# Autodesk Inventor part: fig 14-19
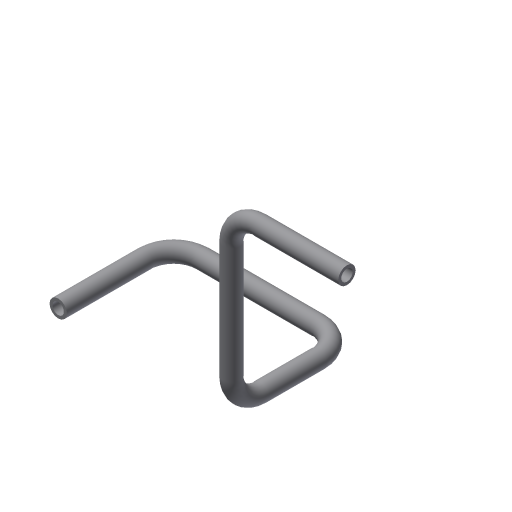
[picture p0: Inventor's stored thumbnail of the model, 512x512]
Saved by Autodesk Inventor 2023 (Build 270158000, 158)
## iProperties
Created: 2005-03
Part Number: fig 14-19
Document SubType Name: Modeling
Designer: CADCIM
Manufacturer: Standard
Standards Organization: Custom
Density: 1 g/cm^3
Material: Generic
Appearance: Default
Author: CADCIM
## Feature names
1. Sweep1
## Parameters: d9 = 6 mm, d10 = 4 mm, d11 = 0, d12 = 0
